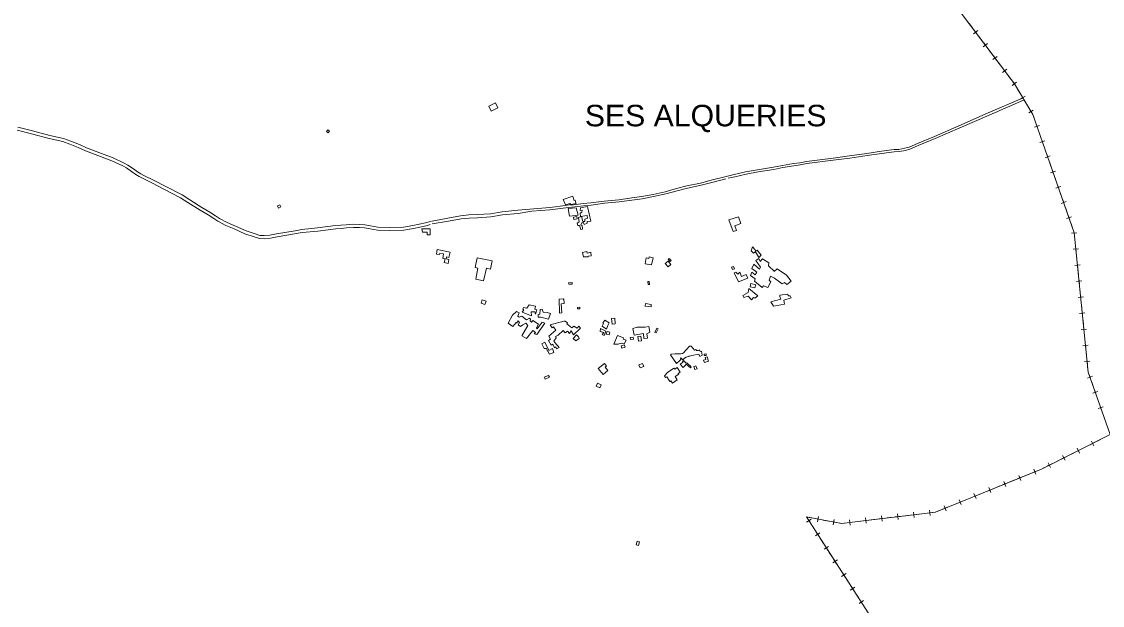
# Model space of a CAD drawing. Extents: x 476989 to 498418, y 4381813 to 4416555.
# Drawn here: x 485650 to 487660, y 4386748 to 4387833 of the extents above; entities that cross this region are included whole.
import ezdxf
from ezdxf.enums import TextEntityAlignment as Align

# ---------------------------------------------------------------- set-up
doc = ezdxf.new("R2010")
doc.units = 0
doc.header["$LTSCALE"] = 20
doc.linetypes.add('MEDIUM_DASHED', pattern=[4.5, 3, -1.5])
for name, color, linetype, lineweight in [('34', 7, 'Continuous', 13), ('36', 7, 'Continuous', 13), ('47', 7, 'Continuous', 13), ('48', 7, 'MEDIUM_DASHED', 13)]:
    doc.layers.add(name, color=color, linetype=linetype, lineweight=lineweight)
doc.layers.add('7', color=7, linetype='Continuous')

msp = doc.modelspace()

# ---------------------------------------------------------------- linework, layer by layer
at = {"layer": '34'}
for p, q in [((487412.6, 4387829.12), (487418.62, 4387821.13)), ((487428.62, 4387816.16), (487420.63, 4387810.14)), ((487421.62, 4387817.14), (487427.63, 4387809.15)), ((487430.64, 4387805.16), (487436.65, 4387797.17)), ((487446.66, 4387792.19), (487438.67, 4387786.18)), ((487439.65, 4387793.18), (487445.67, 4387785.19)), ((487448.67, 4387781.2), (487454.69, 4387773.21)), ((487464.69, 4387768.23), (487456.7, 4387762.22)), ((487457.69, 4387769.22), (487463.7, 4387761.23)), ((487466.71, 4387757.24), (487472.72, 4387749.25)), ((487482.73, 4387744.27), (487474.74, 4387738.26)), ((487475.73, 4387745.26), (487481.74, 4387737.27)), ((487484.75, 4387733.28), (487490.76, 4387725.29)), ((487500.76, 4387720.31), (487492.77, 4387714.3)), ((487501.93, 4387708.74), (487507.05, 4387700.15)), ((487509.61, 4387695.87), (487514.73, 4387687.28)), ((487516.46, 4387694.14), (487507.87, 4387689.01)), ((487517.29, 4387682.99), (487522.41, 4387674.4)), ((487531.82, 4387668.38), (487523.24, 4387663.26)), ((487524.97, 4387670.11), (487530.09, 4387661.52)), ((487532.07, 4387656.96), (487535.37, 4387647.52)), ((487543.39, 4387639.74), (487533.95, 4387636.44)), ((487537.02, 4387642.81), (487540.32, 4387633.37)), ((487541.97, 4387628.65), (487545.28, 4387619.21)), ((487546.92, 4387614.5), (487550.23, 4387605.06)), ((487553.3, 4387611.43), (487543.86, 4387608.13)), ((487551.88, 4387600.34), (487555.18, 4387590.9)), ((487563.2, 4387583.13), (487553.76, 4387579.82)), ((487556.83, 4387586.19), (487560.14, 4387576.76)), ((487561.79, 4387572.04), (487565.09, 4387562.6)), ((487573.11, 4387554.82), (487563.67, 4387551.52)), ((487566.74, 4387557.89), (487570.04, 4387548.45)), ((487571.69, 4387543.73), (487575, 4387534.29)), ((487583.02, 4387526.51), (487573.58, 4387523.21)), ((487576.65, 4387529.58), (487579.95, 4387520.14)), ((487581.6, 4387515.42), (487584.91, 4387505.99)), ((487592.92, 4387498.21), (487583.49, 4387494.9)), ((487586.55, 4387501.28), (487589.86, 4387491.84)), ((487591.51, 4387487.12), (487594.81, 4387477.68)), ((487602.83, 4387469.9), (487593.39, 4387466.6)), ((487596.46, 4387472.97), (487599.76, 4387463.53)), ((487601.42, 4387458.81), (487604.72, 4387449.37)), ((487612.98, 4387440.44), (487603.03, 4387439.44)), ((487609, 4387429.99), (487610, 4387420.04)), ((487610.5, 4387415.08), (487611.5, 4387405.13)), ((487615.98, 4387410.6), (487606.03, 4387409.6)), ((487612, 4387400.15), (487613, 4387390.2)), ((487618.97, 4387380.76), (487609.02, 4387379.76)), ((487613.5, 4387385.24), (487614.5, 4387375.29)), ((487615, 4387370.31), (487615.99, 4387360.36)), ((487616.49, 4387355.4), (487617.49, 4387345.45)), ((487621.97, 4387350.92), (487612.02, 4387349.92)), ((487617.99, 4387340.47), (487618.99, 4387330.52)), ((487624.96, 4387321.08), (487615.01, 4387320.08)), ((487619.49, 4387325.56), (487620.49, 4387315.61)), ((487620.99, 4387310.63), (487621.99, 4387300.68)), ((487622.48, 4387295.72), (487623.48, 4387285.77)), ((487627.96, 4387291.24), (487618.01, 4387290.24)), ((487623.98, 4387280.79), (487624.98, 4387270.84)), ((487630.95, 4387261.4), (487621, 4387260.4)), ((487625.48, 4387265.88), (487626.48, 4387255.93)), ((487626.98, 4387250.95), (487627.98, 4387241)), ((487628.48, 4387236.04), (487629.47, 4387226.09)), ((487633.95, 4387231.56), (487624, 4387230.56)), ((487629.97, 4387221.11), (487630.97, 4387211.16)), ((487636.95, 4387201.72), (487627, 4387200.72)), ((487631.47, 4387206.2), (487632.47, 4387196.25)), ((487641.94, 4387173.55), (487632.51, 4387170.22)), ((487632.97, 4387191.27), (487633.97, 4387181.32)), ((487635.56, 4387176.6), (487638.89, 4387167.17)), ((487640.55, 4387162.46), (487643.89, 4387153.03)), ((487651.93, 4387145.27), (487642.5, 4387141.94)), ((487645.55, 4387148.32), (487648.88, 4387138.89)), ((487650.55, 4387134.18), (487653.88, 4387124.75)), ((487661.92, 4387117), (487652.5, 4387113.67)), ((487655.54, 4387120.05), (487658.88, 4387110.62)), ((487644.51, 4387044.17), (487640.04, 4387053.11)), ((487660.16, 4387057.58), (487651.21, 4387053.11)), ((487619.92, 4387037.46), (487610.98, 4387032.99)), ((487617.69, 4387030.75), (487613.22, 4387039.7)), ((487633.33, 4387044.17), (487624.39, 4387039.69)), ((487646.75, 4387050.87), (487637.8, 4387046.4)), ((487564.04, 4387003.93), (487559.57, 4387012.87)), ((487579.68, 4387017.34), (487570.74, 4387012.87)), ((487593.1, 4387024.05), (487584.16, 4387019.58)), ((487590.87, 4387017.34), (487586.39, 4387026.29)), ((487606.51, 4387030.75), (487597.56, 4387026.28)), ((487525.28, 4386992.18), (487516.02, 4386988.42)), ((487539.18, 4386997.83), (487529.92, 4386994.06)), ((487536.43, 4386991.31), (487532.67, 4387000.58)), ((487566.28, 4387010.64), (487557.33, 4387006.17)), ((487483.61, 4386975.26), (487474.34, 4386971.5)), ((487480.86, 4386968.74), (487477.1, 4386978.01)), ((487497.5, 4386980.9), (487488.23, 4386977.14)), ((487511.4, 4386986.54), (487502.13, 4386982.78)), ((487508.64, 4386980.03), (487504.88, 4386989.29)), ((487428.04, 4386952.69), (487418.77, 4386948.93)), ((487425.29, 4386946.18), (487421.52, 4386955.44)), ((487441.93, 4386958.33), (487432.66, 4386954.57)), ((487455.82, 4386963.97), (487446.56, 4386960.21)), ((487453.07, 4386957.46), (487449.31, 4386966.73)), ((487469.71, 4386969.61), (487460.45, 4386965.85)), ((487369.71, 4386923.61), (487365.95, 4386932.87)), ((487386.35, 4386935.76), (487377.09, 4386932)), ((487400.25, 4386941.41), (487390.99, 4386937.64)), ((487397.5, 4386934.89), (487393.74, 4386944.16)), ((487414.14, 4386947.05), (487404.87, 4386943.28)), ((487121.49, 4386909.88), (487111.65, 4386911.69)), ((487130.41, 4386903.15), (487132.23, 4386912.98)), ((487250.6, 4386904.04), (487249.41, 4386913.96)), ((487269.85, 4386911.38), (487259.92, 4386910.19)), ((487284.74, 4386913.17), (487274.82, 4386911.98)), ((487280.38, 4386907.61), (487279.18, 4386917.54)), ((487299.63, 4386914.96), (487289.7, 4386913.76)), ((487314.52, 4386916.74), (487304.59, 4386915.55)), ((487310.15, 4386911.18), (487308.96, 4386921.11)), ((487329.4, 4386918.53), (487319.48, 4386917.34)), ((487344.3, 4386920.32), (487334.37, 4386919.12)), ((487339.93, 4386914.76), (487338.74, 4386924.68)), ((487372.46, 4386930.12), (487363.2, 4386926.36)), ((487118.7, 4386907.72), (487110.3, 4386902.31)), ((487111.79, 4386909.22), (487117.21, 4386900.81)), ((487119.92, 4386896.61), (487125.33, 4386888.2)), ((487136.24, 4386907.16), (487126.4, 4386908.97)), ((487150.98, 4386904.43), (487141.14, 4386906.25)), ((487165.73, 4386901.71), (487155.9, 4386903.53)), ((487159.9, 4386897.7), (487161.72, 4386907.54)), ((487195.42, 4386902.45), (487185.49, 4386901.26)), ((487191.05, 4386896.89), (487189.86, 4386906.82)), ((487210.3, 4386904.24), (487200.37, 4386903.04)), ((487225.19, 4386906.02), (487215.26, 4386904.83)), ((487220.82, 4386900.46), (487219.63, 4386910.39)), ((487240.08, 4386907.81), (487230.15, 4386906.62)), ((487254.97, 4386909.6), (487245.04, 4386908.4)), ((487134.95, 4386882.51), (487126.54, 4386877.1)), ((487128.04, 4386884.01), (487133.45, 4386875.6)), ((487136.16, 4386871.4), (487141.58, 4386862.99)), ((487151.19, 4386857.3), (487142.79, 4386851.89)), ((487144.28, 4386858.8), (487149.7, 4386850.39)), ((487152.41, 4386846.19), (487157.82, 4386837.78)), ((487167.44, 4386832.1), (487159.03, 4386826.68)), ((487160.53, 4386833.59), (487165.94, 4386825.18)), ((487168.65, 4386820.98), (487174.07, 4386812.58)), ((487183.68, 4386806.89), (487175.28, 4386801.47)), ((487176.77, 4386808.38), (487182.19, 4386799.97)), ((487184.9, 4386795.77), (487190.31, 4386787.37)), ((487199.93, 4386781.68), (487191.52, 4386776.26)), ((487193.02, 4386783.17), (487198.43, 4386774.77)), ((487201.14, 4386770.56), (487206.56, 4386762.16)), ((487216.17, 4386756.47), (487207.77, 4386751.05)), ((487209.26, 4386757.96), (487214.68, 4386749.56))]:
    msp.add_line(p, q, dxfattribs=at)
for points in [[(486520.9, 4388755.72), (486603, 4388633), (486612, 4388581), (486746, 4388393), (486776, 4388338), (486812, 4388290), (486879, 4388250), (487017, 4388189), (487152, 4388148), (487234, 4388140), (487360, 4387899), (487497, 4387717), (487531, 4387660), (487608, 4387440), (487634, 4387181), (487675, 4387065), (487547, 4387001), (487350, 4386921), (487175, 4386900), (487110, 4386912), (487380, 4386493), (487280.6, 4386441.97)], [(487493.76, 4387721.3), (487497, 4387717), (487499.36, 4387713.04)], [(487606.37, 4387444.66), (487608, 4387440), (487608.51, 4387434.97)], [(487552.86, 4387003.93), (487547, 4387001), (487543.81, 4386999.7)], [(487358.57, 4386924.48), (487350, 4386921), (487349.25, 4386920.91)], [(487180.52, 4386900.66), (487175, 4386900), (487170.64, 4386900.81)]]:
    msp.add_lwpolyline(points, dxfattribs=at)
at = {"layer": '36'}
for points in [[(486681.81, 4387493.08), (486694.64, 4387494.43), (486708.83, 4387495.72), (486733.93, 4387499.19), (486761.2, 4387501.8), (486789.75, 4387505.79), (486803.91, 4387507.68), (486824.62, 4387511.62), (486847.35, 4387516.42), (486868.27, 4387522.32), (486887.64, 4387527.27), (486913.13, 4387532.74), (486932.76, 4387537.91), (486960.47, 4387544.96), (486975.67, 4387548.51), (486996.79, 4387553.41), (487019.08, 4387557.56), (487048.39, 4387562.31), (487065.1, 4387565.6), (487086.13, 4387569.01), (487097.8, 4387570.4), (487109.95, 4387572.95), (487159.3, 4387579.14), (487190.28, 4387583.2), (487222.47, 4387587.83), (487249.22, 4387591.96), (487272.87, 4387594.88), (487281.57, 4387595.35), (487293.04, 4387597.4), (487301.06, 4387599.65), (487316.2, 4387606.51), (487347.8, 4387619.2), (487393.55, 4387638.93), (487448.21, 4387662.97), (487511.52, 4387690.61)], [(486964.24, 4387541.72), (486976.62, 4387544.44), (486997.64, 4387549.32), (487019.8, 4387553.44), (487049.13, 4387558.2), (487065.84, 4387561.49), (487086.71, 4387564.87), (487098.48, 4387566.27), (487110.55, 4387568.8), (487159.87, 4387575), (487190.84, 4387579.06), (487223.09, 4387583.7), (487249.79, 4387587.82), (487273.23, 4387590.72), (487282.06, 4387591.19), (487293.97, 4387593.33), (487302.49, 4387595.71), (487317.85, 4387602.66), (487349.41, 4387615.35), (487395.22, 4387635.1), (487449.89, 4387659.15), (487513.35, 4387686.84), (487513.66, 4387686.96)], [(485643.14, 4387636.43), (485670.12, 4387629.89), (485702.71, 4387621.09), (485728.3, 4387615.4), (485741.97, 4387610.63), (485757.5, 4387604.24), (485770.99, 4387598.04), (485798.82, 4387587.68), (485820.32, 4387579.33), (485840.91, 4387569.8), (485847.92, 4387566.17), (485858.19, 4387559.27), (485865.91, 4387553.53), (485871.63, 4387550.07), (485877.42, 4387546.92), (485896.42, 4387537.64), (485917.43, 4387526.69), (485948.87, 4387510.62), (485962.71, 4387501.42), (485985.53, 4387487.21), (485999.97, 4387478.82), (486010.53, 4387471.69), (486018.26, 4387466.93), (486032.24, 4387459.24), (486047.97, 4387452.71), (486067.73, 4387443.96), (486084.52, 4387438.16), (486093.46, 4387435.34), (486101.37, 4387435.15), (486111.95, 4387436.05), (486124.36, 4387438.5), (486158.65, 4387443.94), (486171.22, 4387446.53), (486200.61, 4387449.41), (486233.99, 4387453.74), (486244.06, 4387454.27), (486253.83, 4387455.33), (486267.28, 4387456.04), (486278.77, 4387455.87), (486288.75, 4387455.13), (486299.24, 4387453.26), (486312.7, 4387450.89), (486334.51, 4387450.35), (486360.31, 4387450.88), (486377.98, 4387454), (486401.45, 4387458.91), (486412.26, 4387462.09)], [(485641.54, 4387630.77), (485668.67, 4387624.2), (485701.31, 4387615.39), (485726.69, 4387609.74), (485739.89, 4387605.13), (485755.16, 4387598.85), (485768.73, 4387592.61), (485796.73, 4387582.18), (485818.02, 4387573.92), (485838.32, 4387564.52), (485844.92, 4387561.11), (485854.8, 4387554.47), (485862.63, 4387548.64), (485868.7, 4387544.98), (485874.73, 4387541.7), (485893.77, 4387532.39), (485914.74, 4387521.47), (485945.9, 4387505.54), (485959.53, 4387496.48), (485982.5, 4387482.18), (485996.85, 4387473.84), (486007.34, 4387466.75), (486015.3, 4387461.85), (486029.69, 4387453.94), (486045.65, 4387447.31), (486065.57, 4387438.48), (486082.67, 4387432.58), (486092.49, 4387429.48), (486101.55, 4387429.27), (486112.77, 4387430.22), (486125.48, 4387432.73), (486172.11, 4387440.71), (486201.27, 4387443.57), (486234.53, 4387447.88), (486244.53, 4387448.41), (486254.3, 4387449.47), (486267.39, 4387450.16), (486278.51, 4387450), (486288.02, 4387449.29), (486298.22, 4387447.47), (486312.11, 4387445.02), (486334.5, 4387444.47), (486360.89, 4387445.01), (486379.09, 4387448.22), (486402.88, 4387453.21), (486410.26, 4387455.38)], [(486598.9, 4387480.47), (486632.81, 4387482.84), (486662.41, 4387486.84), (486695.05, 4387490.27), (486709.31, 4387491.57), (486734.42, 4387495.04), (486761.69, 4387497.65), (486790.31, 4387501.65), (486804.58, 4387503.55), (486825.44, 4387507.52), (486848.35, 4387512.36), (486869.35, 4387518.28), (486888.6, 4387523.19), (486914.1, 4387528.67), (486933.81, 4387533.87), (486959.88, 4387540.27)], [(486632.38, 4387487), (486661.92, 4387490.99), (486681.28, 4387495)], [(486413.56, 4387461.76), (486442.85, 4387467.63), (486466.63, 4387471.94), (486482.05, 4387473.6), (486497.67, 4387474.12), (486522.37, 4387475.65), (486543.65, 4387479.24), (486573.11, 4387482.2), (486632.38, 4387487)], [(486413.64, 4387456.96), (486443.84, 4387461.83), (486467.47, 4387466.12), (486482.46, 4387467.73), (486497.95, 4387468.25), (486523.04, 4387469.8), (486544.43, 4387473.41), (486573.69, 4387476.35), (486598.9, 4387480.47)]]:
    msp.add_lwpolyline(points, dxfattribs=at)
at = {"layer": '47'}
for points in [[(486681.79, 4387493.07), (486672.16, 4387491.55), (486669.88, 4387494.66), (486662.05, 4387492.45), (486657.31, 4387501.97), (486675.11, 4387508.62), (486677.55, 4387500.93), (486679.72, 4387500.83)], [(486681.77, 4387486.46), (486685.26, 4387473.28), (486668.94, 4387470.89), (486666.9, 4387485.4)], [(486702.81, 4387488.86), (486689.51, 4387486.95), (486689.28, 4387481.93), (486692.44, 4387482.41), (486692.39, 4387478.88), (486688.91, 4387476.98), (486689.65, 4387470.82), (486702.2, 4387472.21), (486702.81, 4387467.63), (486697.75, 4387465.6), (486697.92, 4387461.17), (486693.79, 4387460.93), (486691.37, 4387470.42), (486686.02, 4387468.54), (486687.4, 4387460.65), (486683.39, 4387457.85), (486684.98, 4387453.7), (486687.83, 4387454.11), (486690.05, 4387446.65), (486693.36, 4387447.2), (486693.01, 4387453.96), (486690.46, 4387454.15), (486691.88, 4387458.93), (486694.82, 4387460.09), (486696.34, 4387455.94), (486701.85, 4387457.89), (486701.89, 4387461.04), (486708.65, 4387461.77)], [(486682.82, 4387470.77), (486676.87, 4387469.5), (486677.41, 4387464.84), (486683.66, 4387466.48)], [(486988.11, 4387457.61), (486976.94, 4387453.27), (486979.74, 4387444.23), (486973.64, 4387442.81), (486965.47, 4387464.47), (486983.7, 4387469.68)], [(486394.5, 4387447.43), (486409.96, 4387447.66), (486410.13, 4387436.18), (486404.24, 4387436.34), (486404.37, 4387441.42), (486395.98, 4387441.26)], [(487009.7, 4387414.31), (487006.96, 4387406.84), (487011.33, 4387402.58), (487015.65, 4387405.67), (487014.64, 4387408.39)], [(486423.14, 4387409.21), (486446.93, 4387404.29), (486444.89, 4387394.45), (486440.49, 4387395.32), (486439.77, 4387391.68), (486444.84, 4387390.63), (486443.34, 4387383.4), (486436.27, 4387384.85), (486437.68, 4387391.77), (486433.34, 4387392.62), (486435, 4387401.12), (486427.82, 4387402.49), (486427.27, 4387399.61), (486421.83, 4387400.62)], [(486509.27, 4387351.09), (486494.76, 4387353.93), (486498.79, 4387374.52), (486493.86, 4387375.47), (486497.34, 4387393.57), (486525.22, 4387388.19), (486522.26, 4387372.89), (486514.98, 4387374.26)], [(486693.57, 4387403.76), (486695.02, 4387395.26), (486703.65, 4387395.43), (486703.9, 4387397), (486709.38, 4387397.3), (486709.03, 4387403.98), (486701.95, 4387402.51), (486701.39, 4387405.29)], [(486821.62, 4387380.39), (486809.87, 4387382.65), (486811.99, 4387393.69), (486816.99, 4387392.71), (486817.49, 4387395.28), (486824.65, 4387393.85)], [(487014.75, 4387405.91), (487021.42, 4387394.48), (487025.9, 4387398.47), (487018.31, 4387407.96)], [(486852.49, 4387387.75), (486857.88, 4387381.59), (486852.48, 4387376.87), (486847.09, 4387383.03)], [(486856.38, 4387386.79), (486852.4, 4387390.34), (486854.28, 4387392.45), (486858.26, 4387388.9)], [(486970.73, 4387376.37), (486972.49, 4387371.88), (486976.09, 4387373.29), (486974.33, 4387377.78)], [(487081.64, 4387350.32), (487072.72, 4387361.63), (487055.18, 4387372.99), (487049.93, 4387368.41), (487049.87, 4387368.86), (487039.57, 4387378.61), (487039.66, 4387384.39), (487028.28, 4387391.83), (487024.09, 4387387.16), (487021.62, 4387392.6), (487016.01, 4387388.56), (487024.24, 4387376.66), (487022.69, 4387372.93), (487012.16, 4387382.01), (487008.44, 4387373.73), (487017.65, 4387367.07), (487014.8, 4387362.09), (487008.57, 4387367.2), (487006, 4387360.86), (487014.77, 4387354.81), (487012.98, 4387350.33), (487027.45, 4387338.79), (487030.26, 4387341.53), (487038.03, 4387338.57), (487043.8, 4387348.84), (487040.32, 4387352.34), (487043.13, 4387359.73), (487050.73, 4387356.09), (487064.68, 4387345.31), (487069.37, 4387347.95), (487073.37, 4387343.84)], [(487000.61, 4387356.21), (486983.33, 4387349.33), (486975.16, 4387365.73), (486978.78, 4387366.8), (486982.1, 4387363.38), (486986.06, 4387367.15), (486988.87, 4387359.23), (486998.08, 4387362.92), (486998.08, 4387362.92)], [(486674.26, 4387344.83), (486667.77, 4387344.47), (486667.62, 4387347.25), (486674.11, 4387347.61)], [(486817.5, 4387349.83), (486818.08, 4387344.44), (486815.47, 4387344.16), (486814.89, 4387349.55)], [(487019.27, 4387323), (487002.58, 4387336.67), (487001.35, 4387329.49), (486991.66, 4387323.47), (486993.71, 4387319.69), (487001.63, 4387322.5), (487007.76, 4387315.81), (487011.43, 4387320.26), (487013.8, 4387318.5)], [(487014.08, 4387337.93), (487005.48, 4387340.08), (487006.17, 4387346.3), (487015.58, 4387343.24)], [(486506.97, 4387315.93), (486514.07, 4387313.45), (486511.87, 4387307.16), (486504.77, 4387309.64)], [(486650.75, 4387290.61), (486649.85, 4387316.81), (486657.48, 4387317.36), (486657.49, 4387317.1), (486658.65, 4387317.22), (486659.5, 4387308.99), (486653.39, 4387308.4), (486655.04, 4387291.23)], [(487069.09, 4387307.28), (487048.56, 4387303.82), (487043.88, 4387312.22), (487062.18, 4387316.98), (487060.6, 4387321.96), (487060.63, 4387324.29), (487075.29, 4387326.33), (487076, 4387323.01), (487079.53, 4387323.26), (487081.65, 4387319.41), (487067.7, 4387314.8)], [(486608.39, 4387251.38), (486623.48, 4387272.54), (486618.24, 4387273.82), (486608.76, 4387261.5), (486607.66, 4387263.32), (486611.75, 4387270.61), (486600.74, 4387277.3), (486598.59, 4387274.33), (486596.07, 4387276.61), (486596.94, 4387279.6), (486594.57, 4387281.59), (486588.97, 4387278.37), (486580.44, 4387285.09), (486575.83, 4387283.21), (486573.24, 4387285.5), (486575.65, 4387291.69), (486570.74, 4387294.09), (486562.91, 4387286.99), (486555.12, 4387272.32), (486563.66, 4387265.97), (486569.91, 4387273.24), (486570.72, 4387272.18), (486573.71, 4387276.63), (486576.14, 4387273.45), (486573.68, 4387269.36), (486578.29, 4387266.36), (486582.32, 4387269.46), (486588.06, 4387272.38), (486591.67, 4387267.67), (486580.81, 4387248.47), (486588.92, 4387243.48), (486600.69, 4387258.61), (486605.82, 4387254.94), (486603.39, 4387252.72)], [(486598.24, 4387286.11), (486581.15, 4387292.66), (486583.99, 4387297.05), (486582.13, 4387298.2), (486583.38, 4387301.63), (486589.66, 4387300.12), (486594.18, 4387306.58), (486605.77, 4387303.64), (486604.94, 4387298.1), (486608.67, 4387296.99), (486605.93, 4387289.23), (486604.64, 4387293.07), (486598.12, 4387293.39)], [(486629.96, 4387279.81), (486615.6, 4387283.24), (486610.81, 4387283.68), (486610.73, 4387288.64), (486613.96, 4387288.96), (486614.39, 4387297.74), (486618.07, 4387298.21), (486620.09, 4387292.55), (486627.82, 4387292.37), (486634.01, 4387290.1)], [(486688.69, 4387298.92), (486684.37, 4387298.62), (486684.15, 4387301.69), (486688.47, 4387301.99)], [(486810.46, 4387308.66), (486821.17, 4387306.93), (486821.18, 4387302.65), (486809.94, 4387303.72)], [(486689.6, 4387262.97), (486676.74, 4387250.7), (486672.05, 4387258.04), (486669.34, 4387252.83), (486665.59, 4387257.68), (486661.19, 4387254.3), (486657.12, 4387258.86), (486647.85, 4387250.21), (486643.31, 4387247.5), (486643.67, 4387246.67), (486644.47, 4387244.86), (486640.18, 4387238.76), (486641.79, 4387236.04), (486650.14, 4387226.99), (486644.78, 4387224.67), (486643.48, 4387227.99), (486641.13, 4387226.44), (486638.15, 4387233.39), (486635.34, 4387231.11), (486630, 4387240.34), (486634.08, 4387242.3), (486630.55, 4387247.83), (486643.47, 4387259.35), (486639.43, 4387265.26), (486636.78, 4387263.35), (486633.33, 4387269.1), (486658.49, 4387275.95), (486661.12, 4387275.83), (486665.28, 4387272.85), (486664.05, 4387271.14), (486673.33, 4387263.73), (486677.42, 4387266.74), (486683.6, 4387262.9), (486686.35, 4387266.39)], [(486738.05, 4387261.15), (486729.72, 4387266.75), (486732.19, 4387271.44), (486731.46, 4387272.57), (486735.21, 4387278.07), (486743.24, 4387273.08), (486740.47, 4387267.87)], [(486753.34, 4387281.26), (486754.19, 4387271.17), (486748.31, 4387270.68), (486747.46, 4387280.77)], [(486727.03, 4387262.13), (486736.71, 4387257.19), (486733.6, 4387249.28), (486730.17, 4387250.98), (486732.78, 4387254.7), (486726.51, 4387257.04)], [(486742.69, 4387250.35), (486737.52, 4387251.81), (486738.96, 4387256.93), (486744.13, 4387255.47)], [(486806.59, 4387253.19), (486789.73, 4387249.68), (486787.14, 4387262.62), (486795.2, 4387264.76), (486809.98, 4387264.77), (486817.05, 4387266.02), (486818.71, 4387255.57), (486813.04, 4387252.65), (486814.34, 4387244.15), (486807.73, 4387243.57)], [(486834.4, 4387261.64), (486830.63, 4387253.99), (486828.15, 4387255.21), (486831.92, 4387262.86)], [(486617.97, 4387233.61), (486622.2, 4387225.07), (486626.1, 4387225.01), (486628.51, 4387220.4), (486628.66, 4387220.4), (486631.73, 4387214.42), (486640.02, 4387217.53), (486637.28, 4387225.22), (486630.7, 4387221.57), (486623.57, 4387236.9)], [(486681.92, 4387250.7), (486675.89, 4387243.58), (486681.01, 4387239.46), (486687.14, 4387243.57), (486685.99, 4387247.04)], [(486758.36, 4387249.45), (486769.41, 4387245.09), (486768.92, 4387242.62), (486774.67, 4387240.36), (486771.04, 4387233.59), (486766.11, 4387234.86), (486759.93, 4387233.15), (486751.53, 4387233.27)], [(486788.28, 4387242.57), (486782.54, 4387241.81), (486782.02, 4387245.74), (486787.76, 4387246.5)], [(486797.31, 4387238.84), (486796.27, 4387247.46), (486802.02, 4387248.15), (486803.06, 4387239.53)], [(486770.8, 4387232.09), (486765.12, 4387229.83), (486766.8, 4387225.62), (486772.48, 4387227.88)], [(486868.22, 4387197.45), (486857.35, 4387213.44), (486858.19, 4387214.78), (486864.88, 4387215.21), (486871.55, 4387215.12), (486876.13, 4387215.27), (486876.51, 4387215.34), (486878.54, 4387215.84), (486879.44, 4387216.05), (486881.26, 4387217), (486892.46, 4387229.22), (486895.77, 4387229.7), (486901.66, 4387221.81), (486904.08, 4387223.13), (486905.64, 4387221.53), (486908.56, 4387221.56), (486910.07, 4387221.92), (486911.05, 4387222.43), (486912.36, 4387219.63), (486914.7, 4387220.2), (486916.17, 4387213.05), (486911.56, 4387210.56), (486910.04, 4387214.71), (486896.95, 4387212.12), (486892.2, 4387210.84), (486891.52, 4387210.63), (486890.92, 4387210.56), (486887.98, 4387209.48), (486886.39, 4387208.75), (486883.29, 4387206.99), (486879.8, 4387203.89), (486876.55, 4387208.06), (486875.64, 4387207.33), (486876.21, 4387204.77), (486873.77, 4387202.48), (486874.07, 4387202.25)], [(486919.83, 4387211.95), (486923.66, 4387212.18), (486923.48, 4387215.12), (486919.65, 4387214.89)], [(486740.48, 4387184.58), (486735.69, 4387190.72), (486737.89, 4387192.57), (486734.51, 4387197.57), (486722.74, 4387187.98), (486732.04, 4387176.89)], [(486804.97, 4387197.53), (486807.29, 4387191.65), (486800.49, 4387188.97), (486798.17, 4387194.85)], [(486874.8, 4387195.93), (486880.65, 4387190.07), (486884.2, 4387193.62), (486884.1, 4387193.71), (486886.41, 4387196.28), (486894.11, 4387189.35), (486895.63, 4387191.04), (486887.19, 4387198.61), (486886.47, 4387197.82), (486881.06, 4387202.73), (486879.38, 4387200.88), (486880.32, 4387200.01)], [(486900.71, 4387191.74), (486902.59, 4387186.12), (486906.35, 4387187.38), (486904.47, 4387193)], [(486920.17, 4387198.96), (486927.86, 4387201.55), (486925.07, 4387209.82), (486921.31, 4387208.57), (486922.6, 4387204.66), (486918.63, 4387203.36)], [(486630.19, 4387175.2), (486622.2, 4387171.67), (486623.78, 4387168.09), (486631.77, 4387171.62)], [(486851.24, 4387180.36), (486863.52, 4387188.59), (486864.92, 4387186.48), (486869.68, 4387189.65), (486875.18, 4387181.39), (486871.42, 4387178.9), (486872.43, 4387177.36), (486865.55, 4387172.85), (486869.53, 4387166.76), (486860.55, 4387160.89), (486857.85, 4387165.01), (486855.95, 4387163.76), (486850.02, 4387172.75), (486847.96, 4387171.41), (486845.86, 4387174.63)], [(486725.45, 4387151.85), (486718.86, 4387154.86), (486721.52, 4387160.69), (486728.11, 4387157.68)]]:
    msp.add_lwpolyline(points, close=True, dxfattribs=at)
at = {"layer": '48'}
for points in [[(486531.5, 4387681.91), (486518.99, 4387675.77), (486523.62, 4387666.34), (486536.13, 4387672.48)], [(486222.79, 4387629), (486220.04, 4387625.87), (486217.23, 4387628.33), (486219.98, 4387631.46)], [(486125.88, 4387490.15), (486127.64, 4387486.28), (486132, 4387488.26), (486130.24, 4387492.13)], [(486795.28, 4386866.99), (486793.41, 4386860.13), (486797.27, 4386859.08), (486799.14, 4386865.94)]]:
    msp.add_lwpolyline(points, close=True, dxfattribs=at)

# ---------------------------------------------------------------- texts
at = {"layer": '7', "width": 1.05}
msp.add_text('SES ALQUERIES', height=40, dxfattribs=at).set_placement((486922.46, 4387638.12), align=Align.CENTER)

doc.saveas('drawing.dxf')
